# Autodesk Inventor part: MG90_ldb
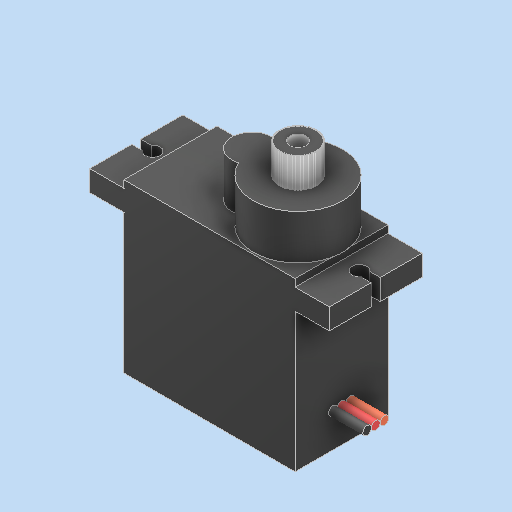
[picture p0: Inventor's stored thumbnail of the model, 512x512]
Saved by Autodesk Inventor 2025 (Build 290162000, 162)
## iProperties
Created: 2019-07
Part Number: MG90_ldb
Material: Steel
Document SubType Name: Modeling
Designer: Ryzen5700u
Density: 7.85 g/cm^3
Appearance: Default
Author: Ryzen5700u
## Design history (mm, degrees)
node "Geometria corretta1"
  node "Schizzo8-Invisible"
feature "Solido1"
sketch "Schizzo2-Invisible"
sketch "Schizzo9-Invisible"
node "Schizzo11-Invisible"
node "Schizzo12-Invisible"
node "Schizzo6-Invisible"
sketch "Schizzo10-Invisible"
node "Schizzo7-Invisible"
node "Schizzo13-Invisible"
node "Solido2"
